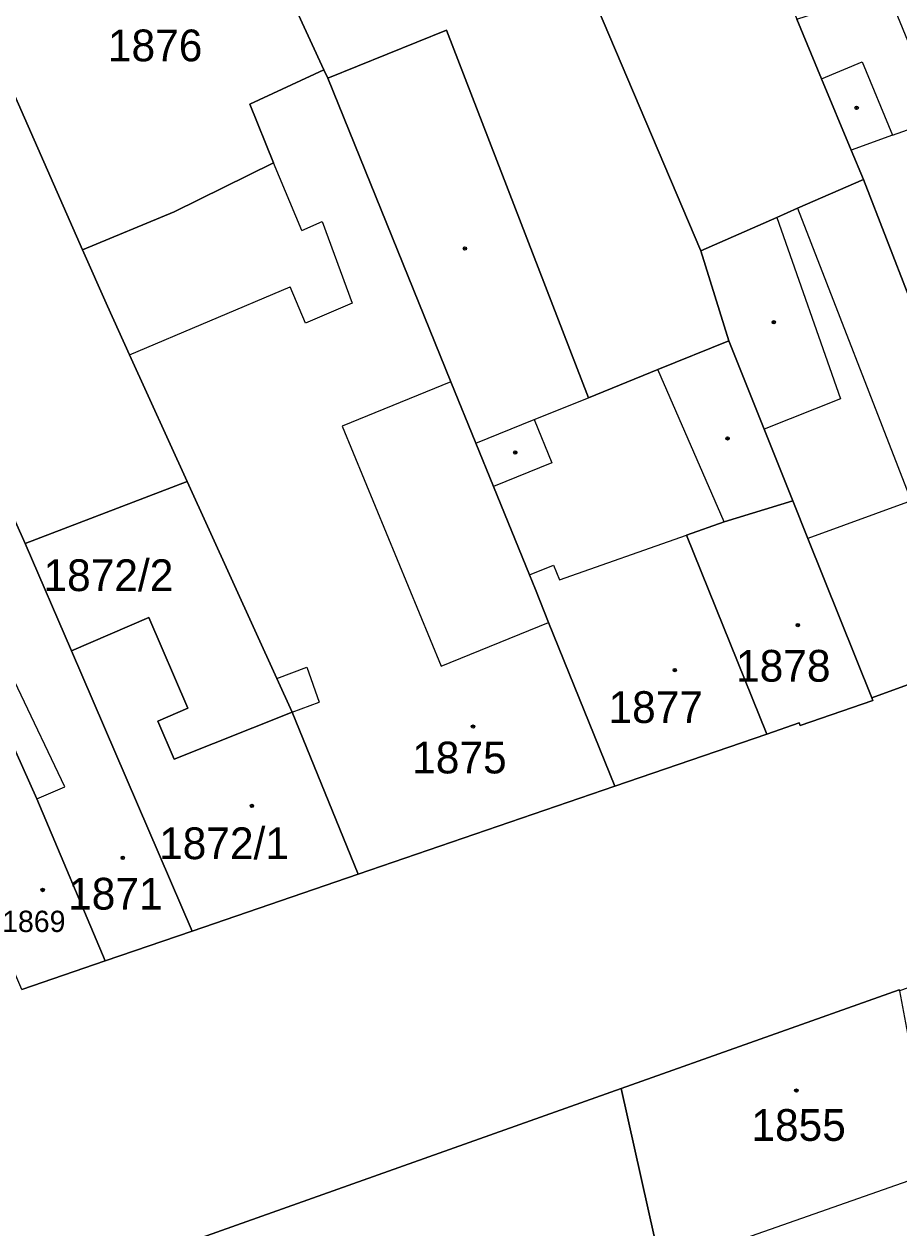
# Model space of a CAD drawing. Extents: x -596233 to -595156, y -1161235 to -1159375.
# Drawn here: x -595853.3 to -595806.5, y -1161150.2 to -1161085.7 of the extents above; entities that cross this region are included whole.
import ezdxf

# ---------------------------------------------------------------- set-up
doc = ezdxf.new("R2010")
doc.units = 0
for name, color, linetype in [('KN_CAR_KR', 7, 'Continuous'), ('KN_KULTURY', 7, 'Continuous'), ('KN_PARC_CIS_POZ', 7, 'Continuous'), ('KN_PARC_CIS_STAV', 7, 'Continuous'), ('KN_PARC_PLOCHA', 7, 'Continuous'), ('parcely_l', 7, 'Continuous')]:
    doc.layers.add(name, color=color, linetype=linetype)

msp = doc.modelspace()

# ---------------------------------------------------------------- linework, layer by layer
at = {"layer": 'KN_CAR_KR'}
for points in [[(-595810.6, -1161088.67), (-595808.43, -1161087.77)], [(-595808.43, -1161087.77), (-595806.8, -1161091.7)], [(-595806.8, -1161091.7), (-595804.29, -1161090.8)], [(-595806.8, -1161091.7), (-595809.01, -1161092.5)], [(-595838.43, -1161096.79), (-595839.94, -1161093.17)], [(-595811.89, -1161095.61), (-595805.81, -1161111.26)], [(-595838.43, -1161096.79), (-595837.33, -1161096.32)], [(-595837.33, -1161096.32), (-595835.73, -1161100.69)], [(-595812.99, -1161096.1), (-595809.59, -1161105.8)], [(-595847.65, -1161103.46), (-595839.05, -1161099.82)], [(-595838.23, -1161101.75), (-595839.05, -1161099.82)], [(-595835.73, -1161100.69), (-595838.23, -1161101.75)], [(-595815.81, -1161112.4), (-595819.37, -1161104.24)], [(-595830.44, -1161104.9), (-595836.27, -1161107.27)], [(-595825.98, -1161106.92), (-595823.08, -1161105.75)], [(-595809.59, -1161105.8), (-595813.67, -1161107.43)], [(-595836.27, -1161107.27), (-595830.96, -1161120.11)], [(-595829.1, -1161108.19), (-595825.98, -1161106.92)], [(-595825.98, -1161106.92), (-595825.04, -1161109.24)], [(-595825.04, -1161109.24), (-595828.16, -1161110.51)], [(-595805.81, -1161111.26), (-595811.33, -1161113.28)], [(-595824.63, -1161115.49), (-595817.83, -1161113.11)], [(-595826.24, -1161115.23), (-595824.95, -1161114.71)], [(-595824.95, -1161114.71), (-595824.63, -1161115.49)], [(-595851.12, -1161126.58), (-595856.16, -1161116.02)], [(-595830.96, -1161120.11), (-595825.21, -1161117.78)], [(-595839.77, -1161120.78), (-595838.16, -1161120.17)], [(-595838.16, -1161120.17), (-595837.5, -1161122.04)], [(-595838.95, -1161122.58), (-595837.5, -1161122.04)], [(-595852.61, -1161127.22), (-595851.12, -1161126.58)], [(-595804.6, -1161147.21), (-595815.39, -1161150.98)]]:
    msp.add_lwpolyline(points, dxfattribs=at)
at = {"layer": 'KN_KULTURY'}
for centre, radius in [((-595808.72, -1161090.23), 0.09), ((-595808.72, -1161090.23), 0.0398), ((-595829.69, -1161097.76), 0.09), ((-595829.69, -1161097.76), 0.0398), ((-595813.16, -1161101.71), 0.09), ((-595813.16, -1161101.71), 0.0398), ((-595815.63, -1161107.93), 0.09), ((-595815.63, -1161107.93), 0.0398), ((-595827, -1161108.68), 0.09), ((-595827, -1161108.68), 0.0398), ((-595811.87, -1161117.92), 0.09), ((-595811.87, -1161117.92), 0.0398), ((-595818.46, -1161120.33), 0.09), ((-595818.46, -1161120.33), 0.0398), ((-595829.26, -1161123.35), 0.09), ((-595829.26, -1161123.35), 0.0398), ((-595841.1, -1161127.6), 0.09), ((-595841.1, -1161127.6), 0.0398), ((-595848.01, -1161130.38), 0.09), ((-595848.01, -1161130.38), 0.0398), ((-595852.3, -1161132.1), 0.09), ((-595852.3, -1161132.1), 0.0398), ((-595811.95, -1161142.84), 0.09), ((-595811.95, -1161142.84), 0.0398)]:
    msp.add_circle(centre, radius, dxfattribs=at)
at = {"layer": 'KN_PARC_PLOCHA'}
for points in [[(-595811.92, -1161085.48), (-595810.6, -1161088.67), (-595809.01, -1161092.5), (-595808.36, -1161094.07), (-595811.89, -1161095.61), (-595812.99, -1161096.1), (-595817.06, -1161097.88), (-595830.46, -1161066.36), (-595824.38, -1161063.74), (-595821.46, -1161062.48)], [(-595817.06, -1161097.88), (-595815.57, -1161102.7), (-595819.37, -1161104.24), (-595823.08, -1161105.75), (-595830.68, -1161086.08), (-595837.03, -1161088.65), (-595837.24, -1161088.2), (-595844.69, -1161072.03), (-595844.28, -1161071.85), (-595830.46, -1161066.36)], [(-595837.24, -1161088.2), (-595841.21, -1161090.03), (-595839.94, -1161093.17), (-595845.26, -1161095.8), (-595850.16, -1161097.83), (-595858.78, -1161078.24), (-595844.69, -1161072.03)], [(-595850.16, -1161097.83), (-595848.83, -1161100.85), (-595847.65, -1161103.46), (-595844.56, -1161110.24), (-595853.24, -1161113.55), (-595856.29, -1161106.76), (-595857.14, -1161107.14), (-595868.2, -1161082.4), (-595862.18, -1161079.61), (-595861.21, -1161079.27), (-595858.78, -1161078.24)], [(-595795.4, -1161113.74), (-595794.32, -1161116.86), (-595798.85, -1161118.51), (-595802.19, -1161109.94), (-595808.36, -1161094.07), (-595809.01, -1161092.5), (-595810.6, -1161088.67), (-595811.92, -1161085.48), (-595807.1, -1161083.92), (-595804.29, -1161090.8), (-595803.14, -1161093.62), (-595802.76, -1161094.55), (-595802.06, -1161096.26), (-595802.2, -1161096.32), (-595797.32, -1161108.16)], [(-595815.57, -1161102.7), (-595813.67, -1161107.43), (-595812.14, -1161111.26), (-595815.81, -1161112.4), (-595817.83, -1161113.11), (-595813.53, -1161123.75), (-595821.66, -1161126.54), (-595825.21, -1161117.78), (-595825.92, -1161116.02), (-595826.24, -1161115.23), (-595828.16, -1161110.51), (-595829.1, -1161108.19), (-595830.44, -1161104.9), (-595837.03, -1161088.65), (-595830.68, -1161086.08), (-595823.08, -1161105.75), (-595819.37, -1161104.24)], [(-595837.03, -1161088.65), (-595830.44, -1161104.9), (-595829.1, -1161108.19), (-595828.16, -1161110.51), (-595826.24, -1161115.23), (-595825.92, -1161116.02), (-595825.21, -1161117.78), (-595821.66, -1161126.54), (-595835.4, -1161131.25), (-595838.95, -1161122.58), (-595839.77, -1161120.78), (-595844.56, -1161110.24), (-595847.65, -1161103.46), (-595848.83, -1161100.85), (-595850.16, -1161097.83), (-595845.26, -1161095.8), (-595839.94, -1161093.17), (-595841.21, -1161090.03), (-595837.24, -1161088.2)], [(-595798.85, -1161118.51), (-595807.91, -1161121.82), (-595811.33, -1161113.28), (-595812.14, -1161111.26), (-595813.67, -1161107.43), (-595815.57, -1161102.7), (-595817.06, -1161097.88), (-595812.99, -1161096.1), (-595811.89, -1161095.61), (-595808.36, -1161094.07), (-595802.19, -1161109.94)], [(-595853.24, -1161113.55), (-595850.76, -1161119.29), (-595844.29, -1161134.3), (-595848.96, -1161135.89), (-595852.61, -1161127.22), (-595858.25, -1161114.64), (-595860.87, -1161109.2), (-595859.88, -1161108.37), (-595857.14, -1161107.14), (-595856.29, -1161106.76)], [(-595848.96, -1161135.89), (-595853.42, -1161137.42), (-595857, -1161129.1), (-595862.97, -1161117.08), (-595863.23, -1161116.56), (-595865.9, -1161111.18), (-595860.87, -1161109.2), (-595858.25, -1161114.64), (-595852.61, -1161127.22)], [(-595838.95, -1161122.58), (-595845.26, -1161125.09), (-595846.13, -1161123.06), (-595844.52, -1161122.37), (-595846.62, -1161117.51), (-595850.76, -1161119.29), (-595853.24, -1161113.55), (-595844.56, -1161110.24), (-595839.77, -1161120.78)], [(-595807.91, -1161121.82), (-595807.86, -1161121.96), (-595811.74, -1161123.29), (-595811.79, -1161123.15), (-595813.53, -1161123.75), (-595817.83, -1161113.11), (-595815.81, -1161112.4), (-595812.14, -1161111.26), (-595811.33, -1161113.28)], [(-595838.95, -1161122.58), (-595835.4, -1161131.25), (-595844.29, -1161134.3), (-595850.76, -1161119.29), (-595846.62, -1161117.51), (-595844.52, -1161122.37), (-595846.13, -1161123.06), (-595845.26, -1161125.09)], [(-595806.43, -1161137.5), (-595804.6, -1161147.21), (-595804.54, -1161147.52), (-595804.4, -1161153.35), (-595804.27, -1161154.44), (-595804.01, -1161156.61), (-595803.46, -1161161.2), (-595803.13, -1161166.05), (-595802.85, -1161168.78), (-595804.68, -1161169.1), (-595811.11, -1161170.22), (-595810.69, -1161174.11), (-595810.55, -1161175.3), (-595816.91, -1161176.05), (-595817.05, -1161174.85), (-595817.31, -1161172.62), (-595817.56, -1161169.3), (-595819.18, -1161152.3), (-595821.33, -1161142.73), (-595806.45, -1161137.45)], [(-595817.56, -1161169.3), (-595822.68, -1161170.07), (-595826.45, -1161170.63), (-595830.17, -1161171.19), (-595830.51, -1161171.24), (-595844.09, -1161172.17), (-595846.2, -1161153.18), (-595844.89, -1161151.09), (-595821.33, -1161142.73), (-595819.18, -1161152.3)]]:
    msp.add_lwpolyline(points, close=True, dxfattribs=at)
for points in [[(-595729.91, -1161110.67), (-595735.77, -1161112.73), (-595741.74, -1161115.13), (-595741.52, -1161115.7), (-595751.36, -1161119.02), (-595751.42, -1161118.6), (-595759.3, -1161121.21), (-595759.27, -1161121.41), (-595766.95, -1161123.64), (-595775.08, -1161126.52), (-595775.1, -1161126.47), (-595778.5, -1161127.58), (-595792.31, -1161132.6), (-595806.43, -1161137.5), (-595806.45, -1161137.45), (-595821.33, -1161142.73), (-595844.89, -1161151.09)], [(-595853.42, -1161137.42), (-595848.96, -1161135.89), (-595844.29, -1161134.3), (-595835.4, -1161131.25), (-595821.66, -1161126.54), (-595813.53, -1161123.75), (-595811.79, -1161123.15), (-595811.74, -1161123.29), (-595807.86, -1161121.96), (-595807.91, -1161121.82), (-595798.85, -1161118.51)]]:
    msp.add_lwpolyline(points, dxfattribs=at)
at = {"layer": 'parcely_l'}
for points in [[(-595830.46, -1161066.36), (-595817.06, -1161097.88)], [(-595837.24, -1161088.2), (-595844.69, -1161072.03)], [(-595858.78, -1161078.24), (-595850.16, -1161097.83)], [(-595815.57, -1161102.7), (-595819.37, -1161104.24), (-595823.08, -1161105.75), (-595830.68, -1161086.08), (-595837.03, -1161088.65)], [(-595811.92, -1161085.48), (-595810.6, -1161088.67), (-595809.01, -1161092.5), (-595808.36, -1161094.07)], [(-595850.16, -1161097.83), (-595845.26, -1161095.8), (-595839.94, -1161093.17), (-595841.21, -1161090.03), (-595837.24, -1161088.2)], [(-595837.03, -1161088.65), (-595837.24, -1161088.2)], [(-595837.03, -1161088.65), (-595830.44, -1161104.9), (-595829.1, -1161108.19), (-595828.16, -1161110.51), (-595826.24, -1161115.23), (-595825.92, -1161116.02), (-595825.21, -1161117.78), (-595821.66, -1161126.54)], [(-595808.36, -1161094.07), (-595811.89, -1161095.61), (-595812.99, -1161096.1), (-595817.06, -1161097.88)], [(-595808.36, -1161094.07), (-595802.19, -1161109.94), (-595798.85, -1161118.51)], [(-595850.16, -1161097.83), (-595848.83, -1161100.85), (-595847.65, -1161103.46), (-595844.56, -1161110.24)], [(-595817.06, -1161097.88), (-595815.57, -1161102.7)], [(-595812.14, -1161111.26), (-595813.67, -1161107.43), (-595815.57, -1161102.7)], [(-595857.14, -1161107.14), (-595856.29, -1161106.76), (-595853.24, -1161113.55)], [(-595860.87, -1161109.2), (-595858.25, -1161114.64), (-595852.61, -1161127.22), (-595848.96, -1161135.89)], [(-595853.24, -1161113.55), (-595844.56, -1161110.24)], [(-595844.56, -1161110.24), (-595839.77, -1161120.78), (-595838.95, -1161122.58)], [(-595813.53, -1161123.75), (-595817.83, -1161113.11), (-595815.81, -1161112.4), (-595812.14, -1161111.26)], [(-595812.14, -1161111.26), (-595811.33, -1161113.28), (-595807.91, -1161121.82)], [(-595850.76, -1161119.29), (-595853.24, -1161113.55)], [(-595838.95, -1161122.58), (-595845.26, -1161125.09), (-595846.13, -1161123.06), (-595844.52, -1161122.37), (-595846.62, -1161117.51), (-595850.76, -1161119.29)], [(-595807.91, -1161121.82), (-595798.85, -1161118.51)], [(-595850.76, -1161119.29), (-595844.29, -1161134.3)], [(-595813.53, -1161123.75), (-595811.79, -1161123.15), (-595811.74, -1161123.29), (-595807.86, -1161121.96), (-595807.91, -1161121.82)], [(-595835.4, -1161131.25), (-595838.95, -1161122.58)], [(-595821.66, -1161126.54), (-595813.53, -1161123.75)], [(-595835.4, -1161131.25), (-595821.66, -1161126.54)], [(-595844.29, -1161134.3), (-595835.4, -1161131.25)], [(-595848.96, -1161135.89), (-595844.29, -1161134.3)], [(-595848.96, -1161135.89), (-595853.42, -1161137.42)], [(-595806.43, -1161137.5), (-595806.45, -1161137.45), (-595821.33, -1161142.73)], [(-595821.33, -1161142.73), (-595844.89, -1161151.09)], [(-595821.33, -1161142.73), (-595819.18, -1161152.3), (-595817.56, -1161169.3)]]:
    msp.add_lwpolyline(points, dxfattribs=at)

# ---------------------------------------------------------------- texts
at = {"layer": 'KN_PARC_CIS_POZ'}
for s, p in [('1876', (-595848.8066, -1161087.74)), ('1872/2', (-595852.2566, -1161116.1))]:
    msp.add_text(s, height=1.7, dxfattribs=at).set_placement(p)
at = {"layer": 'KN_PARC_CIS_STAV'}
for s, height, p in [('1878', 1.7, (-595815.1766, -1161120.95)), ('1877', 1.7, (-595822.0066, -1161123.16)), ('1875', 1.7, (-595832.5166, -1161125.86)), ('1872/1', 1.7, (-595846.0666, -1161130.45)), ('1871', 1.7, (-595850.9366, -1161133.15)), ('1869', 1.14, (-595854.47, -1161134.35)), ('1855', 1.7, (-595814.3566, -1161145.53))]:
    msp.add_text(s, height=height, dxfattribs=at).set_placement(p)

doc.saveas('drawing.dxf')
